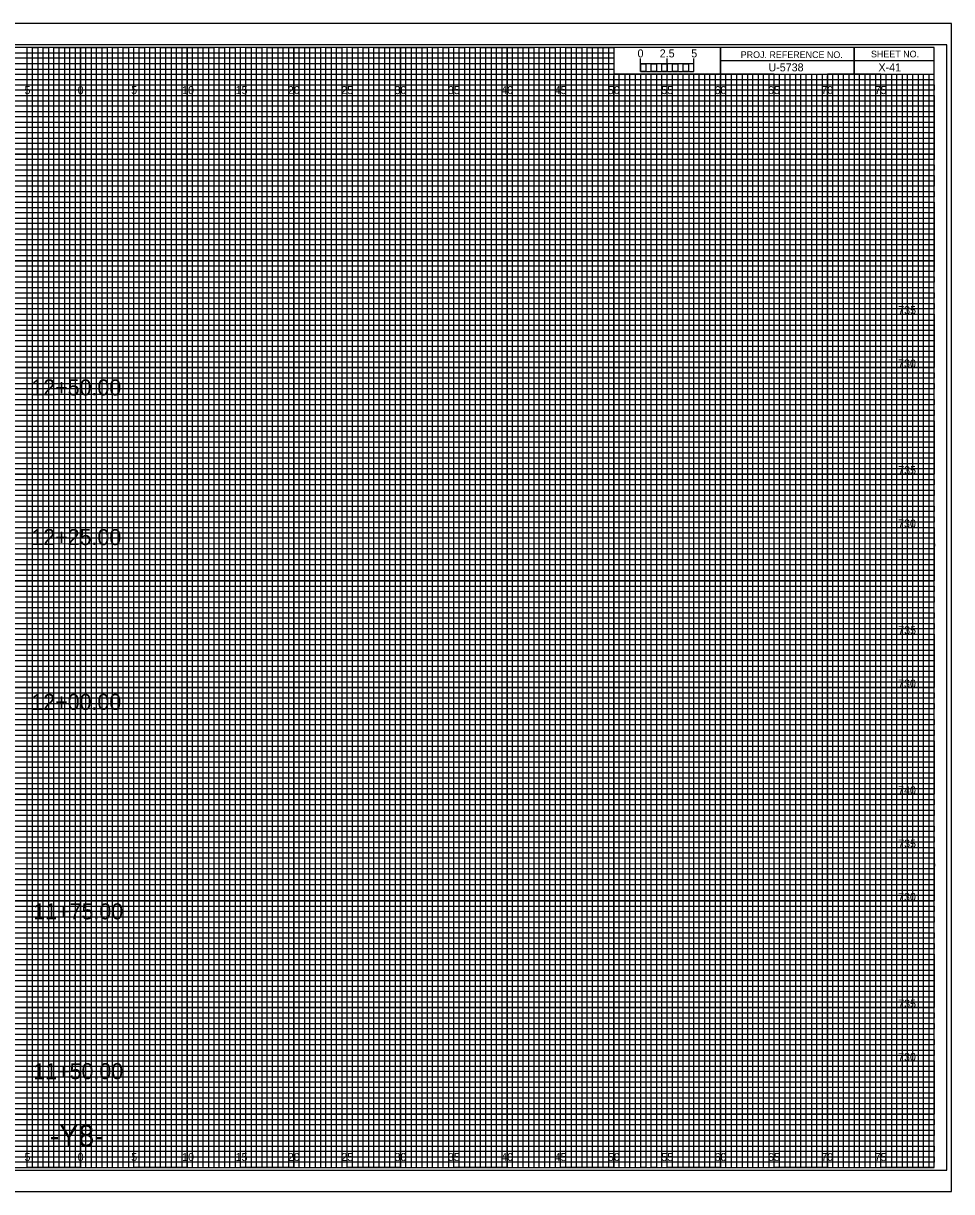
# Model space of a CAD drawing. Extents: x -7 to 162, y 108 to 217.
# Drawn here: x 74.6 to 161.7, y 107.7 to 217.2 of the extents above; entities that cross this region are included whole.
import ezdxf

# ---------------------------------------------------------------- set-up
doc = ezdxf.new("R2010")
doc.units = 0
for name, color, linetype in [('Exist Cross Section Cell', 7, 'Continuous'), ('Exist XS Center Line Elevation Label', 7, 'Continuous'), ('Exist XS Ground Line', 7, 'Continuous'), ('Prop CMT Pvmt Course 1', 7, 'Continuous'), ('Prop CMT Pvmt Course 2', 7, 'Continuous'), ('Prop CMT Pvmt Course 3', 7, 'Continuous'), ('Prop CMT Pvmt Surface', 7, 'Continuous'), ('Prop CMT Pvmt Surface Shoulder', 7, 'Continuous'), ('Prop CMT Shld Paved Course 1', 7, 'Continuous'), ('Prop CMT Shld Paved Course 2', 7, 'Continuous'), ('Prop CMT Shld Paved Course 3', 7, 'Continuous'), ('Prop CMT Slope Grass', 7, 'Continuous'), ('Prop CMT Subgrade Earthwork', 7, 'Continuous'), ('Prop XS Ditch Standard Text', 7, 'Continuous'), ('Prop XS SE Text', 7, 'Continuous'), ('Prop XS Side Slope Text', 7, 'Continuous'), ('Scratch_Level_0', 7, 'Continuous')]:
    doc.layers.add(name, color=color, linetype=linetype)

msp = doc.modelspace()

# ---------------------------------------------------------------- linework, layer by layer
at = {"layer": 'Exist XS Center Line Elevation Label'}
for points in [[(72.5, 110), (77.5, 110), (77.5, 215), (82.5, 215), (82.5, 110), (87.5, 110), (87.5, 215), (92.5, 215), (92.5, 110), (97.5, 110), (97.5, 215), (102.5, 215), (102.5, 110), (107.5, 110), (107.5, 215), (112.5, 215), (112.5, 110), (117.5, 110), (117.5, 215), (122.5, 215), (122.5, 110), (127.5, 110), (127.5, 215), (129.97, 215), (130, 215), (130, 212.5), (132.5, 212.5), (132.5, 110), (137.5, 110), (137.5, 212.5), (142.5, 212.5), (142.5, 110), (147.5, 110), (147.5, 212.5), (152.5, 212.5), (152.5, 110), (157.5, 110), (157.5, 212.5)], [(0, 212.5), (137.5, 212.5)], [(0, 202.5), (160, 202.5), (160, 207.5), (0, 207.5)], [(0, 192.5), (160, 192.5), (160, 197.5), (0, 197.5)], [(0, 182.5), (160, 182.5), (160, 187.5), (0, 187.5)], [(0, 172.5), (160, 172.5), (160, 177.5), (0, 177.5)], [(0, 162.5), (160, 162.5), (160, 167.5), (0, 167.5)], [(0, 152.5), (160, 152.5), (160, 157.5), (0, 157.5)], [(0, 142.5), (160, 142.5), (160, 147.5), (0, 147.5)], [(0, 132.5), (160, 132.5), (160, 137.5), (0, 137.5)], [(0, 122.5), (160, 122.5), (160, 127.5), (0, 127.5)], [(0, 112.5), (160, 112.5), (160, 117.5), (0, 117.5)]]:
    msp.add_lwpolyline(points, dxfattribs=at)
at = {"layer": 'Exist XS Ground Line'}
for p, q in [((75, 215), (70, 215)), ((75, 110), (75, 215)), ((85, 215), (80, 215)), ((80, 215), (80, 110)), ((85, 110), (85, 215)), ((95, 215), (90, 215)), ((90, 215), (90, 110)), ((95, 110), (95, 215)), ((105, 215), (100, 215)), ((100, 215), (100, 110)), ((105, 110), (105, 215)), ((115, 215), (110, 215)), ((110, 215), (110, 110)), ((115, 110), (115, 215)), ((125, 215), (120, 215)), ((120, 215), (120, 110)), ((125, 110), (125, 215)), ((130, 215), (130, 110)), ((135, 110), (135, 212.5)), ((145, 212.5), (140, 212.5)), ((140, 212.5), (140, 110)), ((145, 110), (145, 212.5)), ((155, 212.5), (150, 212.5)), ((150, 212.5), (150, 110)), ((155, 110), (155, 212.5)), ((80, 110), (75, 110)), ((90, 110), (85, 110)), ((100, 110), (95, 110)), ((110, 110), (105, 110)), ((120, 110), (115, 110)), ((130, 110), (125, 110)), ((140, 110), (135, 110)), ((150, 110), (145, 110)), ((160, 110), (155, 110)), ((160, 110), (160, 110))]:
    msp.add_line(p, q, dxfattribs=at)
for points in [[(0, 210), (160, 210), (160, 205), (0, 205)], [(0, 200), (160, 200), (160, 195), (0, 195)], [(0, 190), (160, 190), (160, 185), (0, 185)], [(0, 180), (160, 180), (160, 175), (0, 175)], [(0, 170), (160, 170), (160, 165), (0, 165)], [(0, 160), (160, 160), (160, 155), (0, 155)], [(0, 150), (160, 150), (160, 145), (0, 145)], [(0, 140), (160, 140), (160, 135), (0, 135)], [(0, 130), (160, 130), (160, 125), (0, 125)], [(0, 120), (160, 120), (160, 115), (0, 115)]]:
    msp.add_lwpolyline(points, dxfattribs=at)
at = {"layer": 'Prop CMT Pvmt Course 1'}
for p, q in [((75, 110), (75, 215)), ((80, 110), (80, 215)), ((85, 110), (85, 215)), ((90, 110), (90, 215)), ((95, 110), (95, 215)), ((100, 110), (100, 215)), ((105, 110), (105, 215)), ((110, 110), (110, 215)), ((115, 110), (115, 215)), ((120, 110), (120, 215)), ((125, 110), (125, 215)), ((130, 110), (130, 212.34)), ((135, 110), (135, 212.34)), ((140, 110), (140, 212.34)), ((145, 110), (145, 212.34)), ((150, 110), (150, 212.34)), ((155, 110), (155, 212.34)), ((0, 210), (160, 210)), ((0, 205), (160, 205)), ((0, 200), (160, 200)), ((0, 195), (160, 195)), ((0, 190), (160, 190)), ((0, 185), (160, 185)), ((0, 180), (160, 180)), ((0, 175), (160, 175)), ((0, 170), (160, 170)), ((0, 165), (160, 165)), ((0, 160), (160, 160)), ((0, 155), (160, 155)), ((0, 150), (160, 150)), ((0, 145), (160, 145)), ((0, 140), (160, 140)), ((0, 135), (160, 135)), ((0, 130), (160, 130)), ((0, 125), (160, 125)), ((0, 120), (160, 120)), ((0, 115), (160, 115))]:
    msp.add_line(p, q, dxfattribs=at)
at = {"layer": 'Prop CMT Pvmt Course 2'}
for p, q in [((161.65, 217.25), (-6.7, 217.25)), ((-6.7, 107.75), (161.65, 107.75))]:
    msp.add_line(p, q, dxfattribs=at)
at = {"layer": 'Prop CMT Pvmt Surface'}
msp.add_lwpolyline([(-6.7, 107.75), (161.65, 107.75), (161.65, 217.25), (-6.7, 217.25)], close=True, dxfattribs=at)
at = {"layer": 'Prop CMT Pvmt Surface Shoulder'}
msp.add_lwpolyline([(-5.4, 109.75), (161.2, 109.75), (161.2, 215.25), (-5.4, 215.25)], close=True, dxfattribs=at)
at = {"layer": 'Prop CMT Shld Paved Course 1'}
for p, q in [((0, 214.5), (130, 214.5)), ((130, 213.99), (0, 213.99)), ((130, 214.5), (130, 213.99)), ((0, 213.5), (130, 213.5)), ((130, 212.94), (0, 212.94)), ((130, 213.5), (130, 212.94)), ((0, 212), (160, 212))]:
    msp.add_line(p, q, dxfattribs=at)
for points in [[(0, 211.5), (135, 211.5), (160, 211.5), (160, 211), (0, 211)], [(0, 210.5), (160, 210.5), (160, 209.5), (0, 209.5)], [(0, 209), (160, 209), (160, 208.5), (0, 208.49)], [(0, 208), (160, 208), (160, 207), (0, 207)], [(0, 206.5), (160, 206.5), (160, 206), (0, 206)], [(0, 205.5), (160, 205.5), (160, 204.5), (0, 204.5)], [(0, 204), (160, 204), (160, 203.5), (0, 203.5)], [(0, 203), (160, 203), (160, 202), (0, 202)], [(0, 201.5), (160, 201.5), (160, 201), (0, 201)], [(0, 200.5), (160, 200.5), (160, 199.5), (0, 199.5)], [(0, 199), (160, 199), (160, 198.5), (0, 198.5)], [(0, 198), (160, 198), (160, 196.97), (160, 196.5), (160, 196), (0, 196)], [(0, 197), (160, 197), (160, 196.5), (0, 196.5)], [(0, 195.5), (160, 195.5), (160, 194.5), (0, 194.52)], [(0, 194.52), (160, 194.5), (160, 194), (0, 194)], [(0, 193.5), (160, 193.5), (160, 193), (0, 193)], [(0, 192), (160, 192), (160, 191.5), (0, 191.5)], [(0, 191), (160, 191), (160, 190.5), (0, 190.5)], [(-0.04, 189.44), (160, 189.44), (160, 188.94), (-0.04, 188.94)], [(0, 188.5), (160, 188.5), (160, 188), (0, 188)], [(0, 187), (160, 187), (160, 186.5), (0, 186.5)], [(0, 186), (160, 186), (160, 185.5), (0, 185.5)], [(0, 184.5), (160, 184.5), (160, 184), (0, 184)], [(0, 183.5), (160, 183.5), (160, 183), (0, 183)], [(0, 182), (160, 182), (160, 181.5), (0, 181.5)], [(0, 181), (160, 181), (160, 180.5), (0, 180.5)], [(0, 179.5), (160, 179.5), (160, 178.99), (0, 179)], [(0, 178.5), (160, 178.5), (160, 178), (0, 178)], [(0, 177), (160, 177), (160, 176.5), (0, 176.5)], [(0, 176), (160, 176), (160, 175.5), (0, 175.5)], [(0, 174.5), (160, 174.5), (160, 174), (0, 174)], [(0, 173.5), (160, 173.5), (160, 173), (0, 173)], [(0, 172), (160, 172), (160, 171.5), (0, 171.5)], [(0, 171), (160, 171), (160, 170.5), (0, 170.5)], [(0, 169.5), (160, 169.5), (160, 169), (0, 169)], [(0, 168.5), (160.03, 168.46), (160, 168), (0, 168)], [(0, 167), (160, 167), (160, 166.5), (0, 166.5)], [(0, 166), (160, 166), (160, 165.5), (0, 165.5)], [(0, 164.5), (160, 164.5), (160, 164), (0, 164)], [(0, 163.5), (160, 163.5), (160, 163), (0, 163)], [(0, 162), (160, 162), (160, 161.5), (0, 161.5)], [(0, 161), (160, 161), (160, 160.5), (0, 160.5)], [(0, 159.5), (160, 159.5), (160, 159), (0, 159)], [(0, 158.5), (160, 158.5), (160, 158), (0, 158)], [(0, 157), (160, 157), (160, 156.5), (0, 156.5)], [(0, 156), (160, 156), (160, 155.5), (0, 155.5)], [(0, 154.5), (160, 154.5), (160, 154), (0, 154)], [(0, 153.5), (160, 153.5), (160, 153), (0, 153)], [(0, 152), (160, 152), (160, 151.5), (0, 151.5)], [(0, 151), (160, 151), (160, 150.5), (0, 150.5)], [(0, 149.5), (160, 149.5), (160, 148.99), (0, 149)], [(0, 148.5), (160, 148.5), (160, 148), (0, 148)], [(0, 147), (160, 147), (160, 146.5), (0, 146.5)], [(0, 146), (160, 146), (160, 145.5), (0, 145.5)], [(0, 144.5), (160, 144.5), (160, 144), (0, 144)], [(0, 143.5), (160, 143.5), (160, 143), (0, 143)], [(0, 142), (160, 142), (160, 141.5), (0, 141.5)], [(0, 141), (160, 141), (160, 140.5), (0, 140.5)], [(0, 139.5), (160, 139.5), (160, 139), (0, 139)], [(0, 138.5), (160.03, 138.46), (160, 138), (0, 138)], [(0, 137), (160, 137), (160, 136.5), (0, 136.5)], [(0, 136), (160, 136), (160, 135.5), (0, 135.5)], [(0, 134.5), (160, 134.5), (160, 134), (0, 134)], [(0, 133.5), (160, 133.5), (160, 133), (0, 133)], [(0, 132), (160, 132), (160, 131.5), (0, 131.5)], [(0, 131), (160, 131), (160, 130.5), (0, 130.5)], [(0, 129.5), (160, 129.5), (160, 129), (0, 129)], [(0, 128.5), (160, 128.5), (160, 128), (0, 128)], [(0, 127), (160, 127), (160, 126.5), (0, 126.5)], [(0, 126), (160, 126), (160, 125.5), (0, 125.5)], [(0, 124.5), (160, 124.5), (160, 124), (0, 124)], [(0, 123.5), (160, 123.5), (160, 123), (0, 123)], [(0, 122), (160, 122), (160, 121.5), (0, 121.5)], [(0, 121), (160, 121), (160, 120.5), (0, 120.5)], [(0, 119.5), (160, 119.5), (160, 119), (0, 119)], [(0, 118.5), (160, 118.5), (160, 118), (0, 118)], [(0, 117), (160, 117), (160, 116.5), (0, 116.5)], [(0, 116), (160, 116), (160, 115.5), (0, 115.5)], [(0, 114.5), (160, 114.5), (160, 114), (0, 114)], [(0, 113.5), (160, 113.5), (160, 113), (0, 113)], [(0, 112), (160, 112), (160, 111.5), (0, 111.5)], [(0, 111), (160, 111), (160, 110.5), (0, 110.5)]]:
    msp.add_lwpolyline(points, dxfattribs=at)
at = {"layer": 'Prop CMT Shld Paved Course 2'}
for p, q in [((152.5, 215), (152.5, 212.5)), ((152.5, 212.5), (152.5, 215)), ((160, 213.75), (140, 213.75)), ((140, 213.75), (140, 212.5)), ((140, 212.5), (160, 212.5))]:
    msp.add_line(p, q, dxfattribs=at)
for points in [[(160, 215), (0, 215), (0, 110), (160, 110)], [(140, 215), (130, 215), (130, 212.52), (140, 212.52)], [(160, 215), (140, 215), (140, 212.5), (160, 212.5)]]:
    msp.add_lwpolyline(points, close=True, dxfattribs=at)
at = {"layer": 'Prop CMT Shld Paved Course 3'}
for p, q in [((133.5, 212.5), (133, 212.5)), ((133, 212.5), (133, 110)), ((133.5, 110), (133.5, 212.5)), ((134.5, 212.5), (134, 212.5)), ((134, 212.5), (134, 110)), ((134.5, 110), (134.5, 212.5)), ((133, 110), (132.5, 110)), ((134, 110), (133.5, 110))]:
    msp.add_line(p, q, dxfattribs=at)
for points in [[(75, 110), (75.5, 110), (75.5, 215), (76, 215), (76, 110)], [(76, 110), (76.5, 110), (76.5, 215), (77, 215), (77, 110)], [(77.5, 110), (78, 110), (78, 215), (78.5, 215), (78.5, 110)], [(78.5, 110), (79, 110), (79, 215), (79.5, 215), (79.5, 110)], [(80, 110), (80.5, 110), (80.5, 215), (81, 215), (81, 110)], [(81, 110), (81.5, 110), (81.5, 215), (82, 215), (82, 110)], [(82.5, 110), (83, 110), (83, 215), (83.5, 215), (83.5, 110)], [(83.5, 110), (84, 110), (84, 215), (84.5, 215), (84.5, 110)], [(85, 110), (85.5, 110), (85.5, 215), (86, 215), (86, 110)], [(86, 110), (86.5, 110), (86.5, 215), (87, 215), (87, 110)], [(87.5, 110), (88, 110), (88, 215), (88.5, 215), (88.5, 110)], [(88.5, 110), (89, 110), (89, 215), (89.5, 215), (89.5, 110)], [(90, 110), (90.5, 110), (90.5, 215), (91, 215), (91, 110)], [(91, 110), (91.5, 110), (91.5, 215), (92, 215), (92, 110)], [(92.5, 110), (93, 110), (93, 215), (93.5, 215), (93.5, 110)], [(93.5, 110), (94, 110), (94, 215), (94.5, 215), (94.5, 110)], [(95, 110), (95.5, 110), (95.5, 215), (96, 215), (96, 110)], [(96, 110), (96.5, 110), (96.5, 215), (97, 215), (97, 110)], [(97.5, 110), (98, 110), (98, 215), (98.5, 215), (98.5, 110)], [(98.5, 110), (99, 110), (99, 215), (99.5, 215), (99.5, 110)], [(100, 110), (100.5, 110), (100.5, 215), (101, 215), (101, 110)], [(101, 110), (101.5, 110), (101.5, 215), (102, 215), (102, 110)], [(102.5, 110), (103, 110), (103, 215), (103.5, 215), (103.5, 110)], [(103.5, 110), (104, 110), (104, 215), (104.5, 215), (104.5, 110)], [(105, 110), (105.5, 110), (105.5, 215), (106, 215), (106, 110)], [(106, 110), (106.5, 110), (106.5, 215), (107, 215), (107, 110)], [(107.5, 110), (108, 110), (108, 215), (108.5, 215), (108.5, 110)], [(108.5, 110), (109, 110), (109, 215), (109.5, 215), (109.5, 110)], [(110, 110), (110.5, 110), (110.5, 215), (111, 215), (111, 110)], [(111, 110), (111.5, 110), (111.5, 215), (112, 215), (112, 110)], [(112.5, 110), (113, 110), (113, 215), (113.5, 215), (113.5, 110)], [(113.5, 110), (114, 110), (114, 215), (114.5, 215), (114.5, 110)], [(115, 110), (115.5, 110), (115.5, 215), (116, 215), (116, 110)], [(116, 110), (116.5, 110), (116.5, 215), (117, 215), (117, 110)], [(117.5, 110), (118, 110), (118, 215), (118.5, 215), (118.5, 110)], [(118.5, 110), (119, 110), (119, 215), (119.5, 215), (119.5, 110)], [(120, 110), (120.5, 110), (120.5, 215), (121, 215), (121, 110)], [(121, 110), (121.5, 110), (121.5, 215), (122, 215), (122, 110)], [(122.5, 110), (123, 110), (123, 215), (123.5, 215), (123.5, 110)], [(123.5, 110), (124, 110), (124, 215), (124.5, 215), (124.5, 110)], [(125, 110), (125.5, 110), (125.5, 215), (126, 215), (126, 110)], [(126, 110), (126.5, 110), (126.5, 215), (127, 215), (127, 110)], [(127.5, 110), (128, 110), (128, 215), (128.5, 215), (128.5, 110)], [(128.5, 110), (129, 110), (129, 215), (129.5, 215), (129.5, 110)], [(130, 110), (130.5, 110), (130.5, 212.5), (131.01, 212.5), (131.01, 110)], [(131, 110), (131.5, 110), (131.5, 212.5), (132, 212.5), (132, 110)], [(135, 110), (135.49, 110), (135.49, 212.5), (136, 212.5), (136, 110)], [(136, 110), (136.5, 110), (136.5, 212.5), (137.03, 212.5), (137.03, 110)], [(137.5, 110), (138, 110), (138, 212.5), (138.5, 212.5), (138.5, 110)], [(138.5, 110), (139, 110), (139, 212.5), (139.5, 212.5), (139.5, 110)], [(140, 110), (140.5, 110), (140.5, 212.5), (141, 212.5), (141, 110)], [(141, 110), (141.5, 110), (141.5, 212.5), (142, 212.5), (142, 110)], [(142.5, 110), (143, 110), (143, 212.5), (143.5, 212.5), (143.5, 110)], [(143.5, 110), (144, 110), (144, 212.5), (144.5, 212.5), (144.5, 110)], [(145, 110), (145.5, 110), (145.5, 212.5), (146, 212.5), (146, 110)], [(146, 110), (146.5, 110), (146.5, 212.5), (147, 212.5), (147, 110)], [(147.5, 110), (148, 110), (148, 212.5), (148.5, 212.5), (148.5, 110)], [(148.5, 110), (149, 110), (149, 212.5), (149.5, 212.5), (149.5, 110)], [(150, 110), (150.5, 110), (150.5, 212.5), (151, 212.5), (151, 110)], [(151, 110), (151.5, 110), (151.5, 212.5), (152, 212.5), (152, 110)], [(152.5, 110), (153, 110), (153, 212.5), (153.5, 212.5), (153.5, 110)], [(153.5, 110), (154, 110), (154, 212.5), (154.5, 212.5), (154.5, 110)], [(155, 110), (155.5, 110), (155.5, 212.5), (156, 212.5), (156, 110)], [(156, 110), (156.5, 110), (156.5, 212.5), (157, 212.5), (157, 110)], [(157.5, 110), (158, 110), (158, 212.5), (158.5, 212.5), (158.5, 110)], [(158.5, 110), (159, 110), (159, 212.5), (159.5, 212.5), (159.5, 110)]]:
    msp.add_lwpolyline(points, dxfattribs=at)
at = {"layer": 'Prop CMT Subgrade Earthwork'}
for p, q in [((132.5, 212.75), (132.5, 213.95)), ((132.5, 213.45), (132.5, 213.95)), ((135, 212.75), (135, 213.95)), ((137.5, 212.75), (137.5, 213.95)), ((137.5, 213.45), (137.5, 213.95))]:
    msp.add_line(p, q, dxfattribs=at)
for points in [[(137.5, 213.45), (132.5, 213.45), (132.5, 212.75), (137.5, 212.75)], [(132.5, 213.45), (133, 213.45), (133, 212.75), (132.5, 212.75)], [(133.5, 213.45), (134, 213.45), (134, 212.75), (133.5, 212.75)], [(134.5, 213.45), (135, 213.45), (135, 212.75), (134.5, 212.75)], [(135.5, 213.45), (136, 213.45), (136, 212.75), (135.5, 212.75)], [(136.5, 213.45), (137, 213.45), (137, 212.75), (136.5, 212.75)]]:
    msp.add_lwpolyline(points, close=True, dxfattribs=at)

# ---------------------------------------------------------------- texts
at = {"layer": 'Exist Cross Section Cell'}
for s, p in [('5', (74.74, 210.62)), ('0', (79.73, 210.62)), ('0', (79.73, 210.62)), ('5', (84.74, 210.62)), ('10', (89.52, 210.62)), ('15', (94.53, 210.62)), ('20', (99.43, 210.62)), ('25', (104.44, 210.62)), ('30', (109.43, 210.62)), ('35', (114.44, 210.62)), ('40', (119.43, 210.62)), ('45', (124.44, 210.62)), ('50', (129.43, 210.62)), ('55', (134.44, 210.62)), ('60', (139.43, 210.62)), ('65', (144.44, 210.62)), ('70', (149.43, 210.62)), ('75', (154.44, 210.62)), ('5', (74.74, 110.62)), ('0', (79.73, 110.62)), ('0', (79.73, 110.62)), ('5', (84.74, 110.62)), ('10', (89.52, 110.62)), ('15', (94.53, 110.62)), ('20', (99.43, 110.62)), ('25', (104.44, 110.62)), ('30', (109.43, 110.62)), ('35', (114.44, 110.62)), ('40', (119.43, 110.62)), ('45', (124.44, 110.62)), ('50', (129.43, 110.62)), ('55', (134.44, 110.62)), ('60', (139.43, 110.62)), ('65', (144.44, 110.62)), ('70', (149.43, 110.62)), ('75', (154.44, 110.62))]:
    msp.add_text(s, height=0.75, dxfattribs=at).set_placement(p)
at = {"layer": 'Prop CMT Pvmt Course 3'}
for s, p in [('735', (156.64, 190)), ('730', (156.63, 185)), ('735', (156.64, 175)), ('730', (156.63, 170)), ('735', (156.64, 160)), ('730', (156.63, 155)), ('740', (156.63, 145)), ('735', (156.64, 140)), ('730', (156.63, 135)), ('735', (156.64, 125)), ('730', (156.63, 120))]:
    msp.add_text(s, height=0.75, dxfattribs=at).set_placement(p)
at = {"layer": 'Prop CMT Shld Paved Course 2'}
for s, p in [('PROJ. REFERENCE NO.', (141.88, 214)), ('SHEET NO.', (154.09, 214.06))]:
    msp.add_text(s, height=0.625, dxfattribs=at).set_placement(p)
at = {"layer": 'Prop CMT Slope Grass'}
for s, p in [('12+50.00', (75.39, 182.38)), ('12+25.00', (75.39, 168.35)), ('12+00.00', (75.39, 152.9)), ('11+75.00', (75.57, 133.27)), ('11+50.00', (75.57, 118.29))]:
    msp.add_text(s, height=1.5, dxfattribs=at).set_placement(p)
at = {"layer": 'Prop CMT Subgrade Earthwork'}
msp.add_text('0', height=0.75, dxfattribs=at).set_placement((132.21, 214.06))
at = {"layer": 'Prop XS Ditch Standard Text'}
for s, p in [('2.5', (134.29, 214.06)), ('5', (137.24, 214.06))]:
    msp.add_text(s, height=0.75, dxfattribs=at).set_placement(p)
at = {"layer": 'Prop XS SE Text'}
msp.add_text('-Y8-', height=2, dxfattribs=at).set_placement((77.12, 112))
at = {"layer": 'Prop XS Side Slope Text'}
msp.add_text('U-5738', height=0.75, dxfattribs=at).set_placement((144.48, 212.75))
at = {"layer": 'Scratch_Level_0'}
msp.add_text('X-41', height=0.75, dxfattribs=at).set_placement((154.79, 212.75))

doc.saveas('drawing.dxf')
